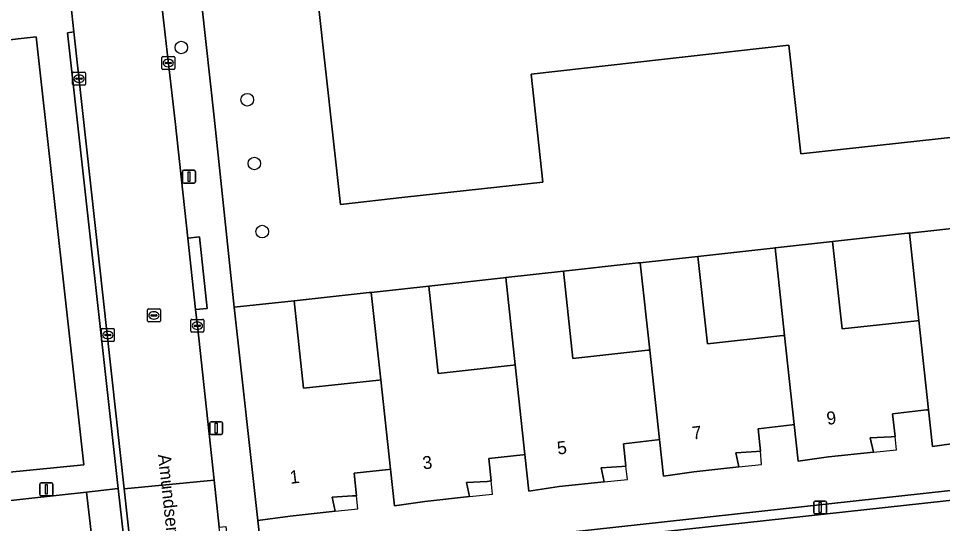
# Model space of a CAD drawing. Extents: x 161248 to 161848, y 384871 to 385383.
# Drawn here: x 161322.9 to 161394.3, y 385161 to 385200.1 of the extents above; entities that cross this region are included whole.
import ezdxf

# ---------------------------------------------------------------- set-up
doc = ezdxf.new("R2010")
doc.units = 0
for name, color, linetype in [('IMGEO_Boom', 7, 'Continuous'), ('IMGEO_Erf', 7, 'Continuous'), ('IMGEO_Kolk', 7, 'Continuous'), ('IMGEO_Lichtmast', 7, 'Continuous'), ('IMGEO_Openbare_ruimte_label', 7, 'Continuous'), ('IMGEO_Pand', 7, 'Continuous'), ('IMGEO_Pand_nummerreeks', 7, 'Continuous'), ('IMGEO_Pand_overbouw', 7, 'Continuous'), ('IMGEO_Rijbaan_lokaal_open', 7, 'Continuous'), ('IMGEO_Rioolput', 7, 'Continuous'), ('IMGEO_Voetpad_open', 7, 'Continuous')]:
    doc.layers.add(name, color=color, linetype=linetype)

msp = doc.modelspace()

# ---------------------------------------------------------------- linework, layer by layer
at = {"layer": 'IMGEO_Boom'}
for centre in [(161335.451, 385197.848), (161340.545, 385193.807), (161341.095, 385188.878), (161341.701, 385183.61)]:
    msp.add_circle(centre, 0.489, dxfattribs=at)
at = {"layer": 'IMGEO_Erf'}
for points in [[(161337.042, 385201.126), (161337.996, 385192.452), (161339.547, 385177.756), (161344.167, 385178.254), (161349.972, 385178.893), (161350.131, 385178.911), (161354.573, 385179.402), (161360.366, 385180.039), (161360.525, 385180.056), (161364.985, 385180.545), (161370.771, 385181.192), (161370.93, 385181.209), (161375.383, 385181.692), (161381.191, 385182.33), (161381.35, 385182.348), (161385.798, 385182.842), (161391.585, 385183.483), (161391.744, 385183.5), (161396.212, 385183.986)], [(161398.94, 385191.336), (161393.97, 385190.79), (161383.334, 385189.623), (161382.412, 385198.032), (161362.486, 385195.783), (161363.403, 385187.435), (161352.721, 385186.262), (161347.75, 385185.717), (161346.037, 385201.322)], [(161395.885, 385167.336), (161393.526, 385167.003), (161393.22, 385169.836), (161393.061, 385169.818), (161390.435, 385169.518), (161390.627, 385167.777), (161390.314, 385167.741), (161388.71, 385167.652), (161388.965, 385166.554), (161385.488, 385166.19), (161383.139, 385165.855), (161382.832, 385168.686), (161382.673, 385168.668), (161380.045, 385168.365), (161380.213, 385166.637), (161379.921, 385166.605), (161378.33, 385166.504), (161378.557, 385165.42), (161375.077, 385165.037), (161372.725, 385164.709), (161372.418, 385167.527), (161372.259, 385167.509), (161369.629, 385167.21), (161369.827, 385165.484), (161369.507, 385165.454), (161367.904, 385165.349), (161368.132, 385164.263), (161364.663, 385163.905), (161362.321, 385163.547), (161362.014, 385166.369), (161361.855, 385166.352), (161359.227, 385166.073), (161359.406, 385164.345), (161359.083, 385164.293), (161357.493, 385164.211), (161357.727, 385163.12), (161354.269, 385162.742), (161351.923, 385162.397), (161351.615, 385165.238), (161351.456, 385165.221), (161348.823, 385164.941), (161348.996, 385163.19), (161348.696, 385163.166), (161347.1, 385163.076), (161347.342, 385161.981), (161343.854, 385161.606), (161341.369, 385161.26), (161341.751, 385157.774), (161414.901, 385165.791)]]:
    msp.add_lwpolyline(points, dxfattribs=at)
for points in [[(161391.744, 385183.5), (161391.585, 385183.483), (161385.798, 385182.842), (161386.549, 385176.083), (161392.321, 385176.723), (161392.474, 385176.74)], [(161381.35, 385182.348), (161381.191, 385182.33), (161375.383, 385181.692), (161376.116, 385174.932), (161381.942, 385175.572), (161382.083, 385175.588)], [(161370.93, 385181.209), (161370.771, 385181.192), (161364.985, 385180.545), (161365.726, 385173.786), (161371.504, 385174.432), (161371.665, 385174.45)], [(161360.525, 385180.056), (161360.366, 385180.039), (161354.573, 385179.402), (161355.319, 385172.643), (161361.107, 385173.279), (161361.26, 385173.296)], [(161350.131, 385178.911), (161349.972, 385178.893), (161344.167, 385178.254), (161344.896, 385171.493), (161350.717, 385172.135), (161350.865, 385172.151)]]:
    msp.add_lwpolyline(points, close=True, dxfattribs=at)
at = {"layer": 'IMGEO_Kolk'}
for p, q in [((161333.937, 385196.219), (161333.937, 385197.071)), ((161334.012, 385197.145), (161334.864, 385197.145)), ((161334.196, 385196.639), (161334.196, 385196.651)), ((161334.634, 385196.602), (161334.236, 385196.602)), ((161334.239, 385196.688), (161334.637, 385196.688)), ((161334.425, 385196.925), (161334.45, 385196.925)), ((161334.68, 385196.651), (161334.68, 385196.639)), ((161334.938, 385197.071), (161334.938, 385196.219)), ((161327.046, 385195.008), (161327.046, 385195.86)), ((161327.121, 385195.934), (161327.973, 385195.934)), ((161328.047, 385195.86), (161328.047, 385195.008)), ((161334.864, 385196.145), (161334.012, 385196.145)), ((161334.448, 385196.365), (161334.423, 385196.365)), ((161327.305, 385195.428), (161327.305, 385195.44)), ((161327.743, 385195.391), (161327.345, 385195.391)), ((161327.348, 385195.477), (161327.746, 385195.477)), ((161327.557, 385195.154), (161327.532, 385195.154)), ((161327.534, 385195.714), (161327.559, 385195.714)), ((161327.789, 385195.44), (161327.789, 385195.428)), ((161327.973, 385194.934), (161327.121, 385194.934)), ((161336.192, 385175.901), (161336.192, 385176.753)), ((161336.267, 385176.827), (161337.119, 385176.827)), ((161336.68, 385176.607), (161336.705, 385176.607)), ((161337.193, 385176.753), (161337.193, 385175.901)), ((161329.269, 385175.193), (161329.269, 385176.045)), ((161329.344, 385176.119), (161330.196, 385176.119)), ((161329.757, 385175.899), (161329.782, 385175.899)), ((161330.27, 385176.045), (161330.27, 385175.193)), ((161337.119, 385175.827), (161336.267, 385175.827)), ((161336.451, 385176.321), (161336.451, 385176.333)), ((161336.889, 385176.284), (161336.491, 385176.284)), ((161336.494, 385176.37), (161336.892, 385176.37)), ((161336.703, 385176.047), (161336.678, 385176.047)), ((161336.935, 385176.333), (161336.935, 385176.321)), ((161330.196, 385175.119), (161329.344, 385175.119)), ((161329.528, 385175.613), (161329.528, 385175.625)), ((161329.966, 385175.576), (161329.568, 385175.576)), ((161329.571, 385175.662), (161329.969, 385175.662)), ((161329.78, 385175.339), (161329.755, 385175.339)), ((161330.012, 385175.625), (161330.012, 385175.613))]:
    msp.add_line(p, q, dxfattribs=at)
for points in [[(161333.937, 385196.219), (161333.937, 385197.071)], [(161334.012, 385197.145), (161334.864, 385197.145)], [(161334.938, 385197.071), (161334.938, 385196.219)], [(161327.046, 385195.008), (161327.046, 385195.86)], [(161327.121, 385195.934), (161327.973, 385195.934)], [(161328.047, 385195.86), (161328.047, 385195.008)], [(161334.864, 385196.145), (161334.012, 385196.145)], [(161327.973, 385194.934), (161327.121, 385194.934)], [(161336.192, 385175.901), (161336.192, 385176.753)], [(161336.267, 385176.827), (161337.119, 385176.827)], [(161337.193, 385176.753), (161337.193, 385175.901)], [(161329.269, 385175.193), (161329.269, 385176.045)], [(161329.344, 385176.119), (161330.196, 385176.119)], [(161330.27, 385176.045), (161330.27, 385175.193)], [(161337.119, 385175.827), (161336.267, 385175.827)], [(161330.196, 385175.119), (161329.344, 385175.119)]]:
    msp.add_lwpolyline(points, dxfattribs=at)
for centre, radius, start, end in [((161334.014, 385197.069), 0.0765, 91.55205, 178.44795), ((161334.014, 385197.069), 0.0765, 91.55205, 178.44795), ((161334.236, 385196.648), 0.0403, 85.87752, 175.75265), ((161334.233, 385196.638), 0.0366, 178.93798, 274.71019), ((161334.637, 385196.645), 0.043, 264.86636, 352.45326), ((161334.641, 385196.65), 0.0386, 1.73085, 96.63898), ((161334.862, 385197.069), 0.0765, 1.55205, 88.44795), ((161334.862, 385197.069), 0.0765, 1.55205, 88.44795), ((161327.123, 385195.858), 0.0765, 91.55205, 178.44795), ((161327.123, 385195.858), 0.0765, 91.55205, 178.44795), ((161327.971, 385195.858), 0.0765, 1.55205, 88.44795), ((161327.971, 385195.858), 0.0765, 1.55205, 88.44795), ((161334.014, 385196.221), 0.0765, 181.55205, 268.44795), ((161334.014, 385196.221), 0.0765, 181.55205, 268.44795), ((161334.862, 385196.221), 0.0765, 271.55205, 358.44795), ((161334.862, 385196.221), 0.0765, 271.55205, 358.44795), ((161327.345, 385195.437), 0.0403, 85.87752, 175.75265), ((161327.342, 385195.427), 0.0366, 178.93798, 274.71019), ((161327.746, 385195.434), 0.043, 264.86636, 352.45326), ((161327.75, 385195.439), 0.0386, 1.73085, 96.63898), ((161327.123, 385195.01), 0.0765, 181.55205, 268.44795), ((161327.123, 385195.01), 0.0765, 181.55205, 268.44795), ((161327.971, 385195.01), 0.0765, 271.55205, 358.44795), ((161327.971, 385195.01), 0.0765, 271.55205, 358.44795), ((161336.269, 385176.751), 0.0765, 91.55205, 178.44795), ((161336.269, 385176.751), 0.0765, 91.55205, 178.44795), ((161337.117, 385176.751), 0.0765, 1.55205, 88.44795), ((161337.117, 385176.751), 0.0765, 1.55205, 88.44795), ((161329.346, 385176.043), 0.0765, 91.55205, 178.44795), ((161329.346, 385176.043), 0.0765, 91.55205, 178.44795), ((161330.194, 385176.043), 0.0765, 1.55205, 88.44795), ((161330.194, 385176.043), 0.0765, 1.55205, 88.44795), ((161336.269, 385175.903), 0.0765, 181.55205, 268.44795), ((161336.269, 385175.903), 0.0765, 181.55205, 268.44795), ((161336.491, 385176.33), 0.0403, 85.87752, 175.75265), ((161336.488, 385176.32), 0.0366, 178.93798, 274.71019), ((161336.892, 385176.327), 0.043, 264.86636, 352.45326), ((161336.896, 385176.332), 0.0386, 1.73085, 96.63898), ((161337.117, 385175.903), 0.0765, 271.55205, 358.44795), ((161337.117, 385175.903), 0.0765, 271.55205, 358.44795), ((161329.346, 385175.195), 0.0765, 181.55205, 268.44795), ((161329.346, 385175.195), 0.0765, 181.55205, 268.44795), ((161329.568, 385175.622), 0.0403, 85.87752, 175.75265), ((161329.565, 385175.612), 0.0366, 178.93798, 274.71019), ((161329.969, 385175.619), 0.043, 264.86636, 352.45326), ((161329.973, 385175.624), 0.0386, 1.73085, 96.63898), ((161330.194, 385175.195), 0.0765, 271.55205, 358.44795), ((161330.194, 385175.195), 0.0765, 271.55205, 358.44795)]:
    msp.add_arc(centre, radius, start, end, dxfattribs=at)
for centre, major_axis, ratio, start_param, end_param in [((161334.424, 385196.645), (-0.387, 0.002), 0.722429, 4.712389, 7.853982), ((161334.449, 385196.645), (-0.39, 0.002), 0.717154, 1.570796, 4.712389), ((161327.533, 385195.434), (-0.387, 0.002), 0.722429, 4.712389, 7.853982), ((161327.558, 385195.434), (-0.39, 0.002), 0.717154, 1.570796, 4.712389), ((161336.679, 385176.327), (-0.387, 0.002), 0.722429, 4.712389, 7.853982), ((161336.704, 385176.327), (-0.39, 0.002), 0.717154, 1.570796, 4.712389), ((161329.756, 385175.619), (-0.387, 0.002), 0.722429, 4.712389, 7.853982), ((161329.781, 385175.619), (-0.39, 0.002), 0.717154, 1.570796, 4.712389)]:
    msp.add_ellipse(centre, major_axis=major_axis, ratio=ratio, start_param=start_param, end_param=end_param, dxfattribs=at)
at = {"layer": 'IMGEO_Lichtmast'}
for p, q in [((161335.547, 385187.463), (161335.547, 385188.263)), ((161335.547, 385188.263), (161335.547, 385187.463)), ((161335.647, 385188.363), (161336.437, 385188.363)), ((161336.437, 385188.363), (161335.647, 385188.363)), ((161336.537, 385188.263), (161336.537, 385187.463)), ((161336.537, 385187.463), (161336.537, 385188.263)), ((161336.437, 385187.363), (161335.647, 385187.363)), ((161335.647, 385187.363), (161336.437, 385187.363)), ((161337.649, 385168.012), (161337.649, 385168.812)), ((161337.649, 385168.812), (161337.649, 385168.012)), ((161337.749, 385168.912), (161338.539, 385168.912)), ((161338.539, 385168.912), (161337.749, 385168.912)), ((161338.639, 385168.812), (161338.639, 385168.012)), ((161338.639, 385168.012), (161338.639, 385168.812)), ((161338.539, 385167.912), (161337.749, 385167.912)), ((161337.749, 385167.912), (161338.539, 385167.912)), ((161324.52, 385163.278), (161324.52, 385164.078)), ((161324.52, 385164.078), (161324.52, 385163.278)), ((161324.62, 385164.178), (161325.41, 385164.178)), ((161325.41, 385164.178), (161324.62, 385164.178)), ((161325.51, 385164.078), (161325.51, 385163.278)), ((161325.51, 385163.278), (161325.51, 385164.078)), ((161325.41, 385163.178), (161324.62, 385163.178)), ((161324.62, 385163.178), (161325.41, 385163.178)), ((161384.342, 385161.877), (161384.342, 385162.677)), ((161384.342, 385162.677), (161384.342, 385161.877)), ((161384.442, 385162.777), (161385.232, 385162.777)), ((161385.232, 385162.777), (161384.442, 385162.777)), ((161385.332, 385162.677), (161385.332, 385161.877)), ((161385.332, 385161.877), (161385.332, 385162.677)), ((161385.232, 385161.777), (161384.442, 385161.777)), ((161384.442, 385161.777), (161385.232, 385161.777))]:
    msp.add_line(p, q, dxfattribs=at)
for points in [[(161335.967, 385188.238), (161336.117, 385188.238), (161336.117, 385187.488), (161335.967, 385187.488), (161335.967, 385188.238)], [(161338.069, 385168.787), (161338.219, 385168.787), (161338.219, 385168.037), (161338.069, 385168.037), (161338.069, 385168.787)], [(161324.94, 385164.053), (161325.09, 385164.053), (161325.09, 385163.303), (161324.94, 385163.303), (161324.94, 385164.053)], [(161384.762, 385162.652), (161384.912, 385162.652), (161384.912, 385161.902), (161384.762, 385161.902), (161384.762, 385162.652)]]:
    msp.add_lwpolyline(points, dxfattribs=at)
for centre, start, end in [((161335.647, 385188.263), 90, 180), ((161335.647, 385188.263), 90, 180), ((161336.437, 385188.263), 0, 90), ((161336.437, 385188.263), 360, 90), ((161335.647, 385187.463), 180, 270), ((161335.647, 385187.463), 180, 270), ((161336.437, 385187.463), 270, 0), ((161336.437, 385187.463), 270, 0), ((161337.749, 385168.812), 90, 180), ((161337.749, 385168.812), 90, 180), ((161338.539, 385168.812), 0, 90), ((161338.539, 385168.812), 360, 90), ((161337.749, 385168.012), 180, 270), ((161337.749, 385168.012), 180, 270), ((161338.539, 385168.012), 270, 0), ((161338.539, 385168.012), 270, 0), ((161324.62, 385164.078), 90, 180), ((161324.62, 385164.078), 90, 180), ((161325.41, 385164.078), 0, 90), ((161325.41, 385164.078), 360, 90), ((161324.62, 385163.278), 180, 270), ((161324.62, 385163.278), 180, 270), ((161325.41, 385163.278), 270, 0), ((161325.41, 385163.278), 270, 0), ((161384.442, 385162.677), 90, 180), ((161384.442, 385162.677), 90, 180), ((161385.232, 385162.677), 0, 90), ((161385.232, 385162.677), 360, 90), ((161384.442, 385161.877), 180, 270), ((161384.442, 385161.877), 180, 270), ((161385.232, 385161.877), 270, 0), ((161385.232, 385161.877), 270, 0)]:
    msp.add_arc(centre, 0.1, start, end, dxfattribs=at)
at = {"layer": 'IMGEO_Pand'}
msp.add_lwpolyline([(161346.037, 385201.322), (161347.75, 385185.717), (161352.721, 385186.262), (161363.403, 385187.435), (161362.486, 385195.783), (161382.412, 385198.032), (161383.334, 385189.623), (161393.97, 385190.79), (161398.94, 385191.336)], dxfattribs=at)
for points in [[(161402.139, 385184.643), (161401.98, 385184.625), (161402.725, 385177.866), (161396.948, 385177.226), (161396.212, 385183.986), (161391.744, 385183.5), (161392.474, 385176.74), (161393.22, 385169.836), (161393.526, 385167.003), (161395.885, 385167.336), (161399.358, 385167.712), (161399.123, 385168.803), (161400.714, 385168.901), (161401.024, 385168.918), (161400.824, 385170.684), (161403.479, 385170.951), (161403.638, 385170.967)], [(161392.474, 385176.74), (161392.321, 385176.723), (161386.549, 385176.083), (161385.798, 385182.842), (161381.35, 385182.348), (161382.083, 385175.588), (161382.832, 385168.686), (161383.139, 385165.855), (161385.488, 385166.19), (161388.965, 385166.554), (161388.71, 385167.652), (161390.314, 385167.741), (161390.627, 385167.777), (161390.435, 385169.518), (161393.061, 385169.818), (161393.22, 385169.836)], [(161382.083, 385175.588), (161381.942, 385175.572), (161376.116, 385174.932), (161375.383, 385181.692), (161370.93, 385181.209), (161371.665, 385174.45), (161372.418, 385167.527), (161372.725, 385164.709), (161375.077, 385165.037), (161378.557, 385165.42), (161378.33, 385166.504), (161379.921, 385166.605), (161380.213, 385166.637), (161380.045, 385168.365), (161382.673, 385168.668), (161382.832, 385168.686)], [(161371.665, 385174.45), (161371.504, 385174.432), (161365.726, 385173.786), (161364.985, 385180.545), (161360.525, 385180.056), (161361.26, 385173.296), (161362.014, 385166.369), (161362.321, 385163.547), (161364.663, 385163.905), (161368.132, 385164.263), (161367.904, 385165.349), (161369.507, 385165.454), (161369.827, 385165.484), (161369.629, 385167.21), (161372.259, 385167.509), (161372.418, 385167.527)], [(161361.26, 385173.296), (161361.107, 385173.279), (161355.319, 385172.643), (161354.573, 385179.402), (161350.131, 385178.911), (161350.865, 385172.151), (161351.615, 385165.238), (161351.923, 385162.397), (161354.269, 385162.742), (161357.727, 385163.12), (161357.493, 385164.211), (161359.083, 385164.293), (161359.406, 385164.345), (161359.227, 385166.073), (161361.855, 385166.352), (161362.014, 385166.369)], [(161350.865, 385172.151), (161350.717, 385172.135), (161344.896, 385171.493), (161344.167, 385178.254), (161339.547, 385177.756), (161341.369, 385161.26), (161343.854, 385161.606), (161347.342, 385161.981), (161347.1, 385163.076), (161348.696, 385163.166), (161348.996, 385163.19), (161348.823, 385164.941), (161351.456, 385165.221), (161351.615, 385165.238)]]:
    msp.add_lwpolyline(points, close=True, dxfattribs=at)
at = {"layer": 'IMGEO_Pand_overbouw'}
for points in [[(161390.627, 385167.777), (161390.314, 385167.741), (161388.71, 385167.652), (161388.965, 385166.554), (161390.741, 385166.74)], [(161380.213, 385166.637), (161379.921, 385166.605), (161378.33, 385166.504), (161378.557, 385165.42), (161380.313, 385165.613)], [(161369.827, 385165.484), (161369.507, 385165.454), (161367.904, 385165.349), (161368.132, 385164.263), (161369.946, 385164.45)], [(161359.406, 385164.345), (161359.083, 385164.293), (161357.493, 385164.211), (161357.727, 385163.12), (161359.513, 385163.315)], [(161348.996, 385163.19), (161348.696, 385163.166), (161347.1, 385163.076), (161347.342, 385161.981), (161349.097, 385162.17)]]:
    msp.add_lwpolyline(points, close=True, dxfattribs=at)
at = {"layer": 'IMGEO_Rijbaan_lokaal_open'}
for points in [[(161326.822, 385201.971), (161327.141, 385199.049), (161331.038, 385163.711), (161337.994, 385164.378), (161336.692, 385176.326), (161336.557, 385177.575), (161335.96, 385183.113), (161334.986, 385192.138), (161334.197, 385198.828), (161333.767, 385202.749)], [(161345.081, 385099.589), (161343.794, 385111.449), (161342.886, 385119.72), (161340.632, 385140.435), (161339.619, 385149.644), (161338.388, 385160.759), (161337.994, 385164.378), (161331.038, 385163.711), (161331.58, 385158.8), (161331.619, 385158.449), (161332.208, 385158.002), (161332.485, 385157.764)], [(161325.63, 385158.041), (161328.7, 385158.391), (161328.129, 385163.466), (161312.135, 385161.71)], [(161395.989, 385162.959), (161342.455, 385157.097), (161342.934, 385152.944), (161343.487, 385152.997), (161349.169, 385153.631), (161353.072, 385154.067), (161358.759, 385154.69), (161362.66, 385155.108), (161368.344, 385155.738), (161372.231, 385156.162), (161377.912, 385156.775), (161381.825, 385157.219), (161387.494, 385157.833), (161392.01, 385158.338), (161396.837, 385114.227)]]:
    msp.add_lwpolyline(points, dxfattribs=at)
at = {"layer": 'IMGEO_Rioolput'}
for p, q in [((161332.831, 385176.701), (161332.831, 385177.553)), ((161332.906, 385177.627), (161333.758, 385177.627)), ((161333.133, 385177.17), (161333.531, 385177.17)), ((161333.319, 385177.407), (161333.344, 385177.407)), ((161333.832, 385177.553), (161333.832, 385176.701)), ((161333.758, 385176.627), (161332.906, 385176.627)), ((161333.09, 385177.121), (161333.09, 385177.133)), ((161333.528, 385177.084), (161333.13, 385177.084)), ((161333.342, 385176.847), (161333.317, 385176.847)), ((161333.574, 385177.133), (161333.574, 385177.121))]:
    msp.add_line(p, q, dxfattribs=at)
for points in [[(161332.831, 385176.701), (161332.831, 385177.553)], [(161332.906, 385177.627), (161333.758, 385177.627)], [(161333.832, 385177.553), (161333.832, 385176.701)], [(161333.758, 385176.627), (161332.906, 385176.627)]]:
    msp.add_lwpolyline(points, dxfattribs=at)
for centre, radius, start, end in [((161332.908, 385177.551), 0.0765, 91.55205, 178.44795), ((161332.908, 385177.551), 0.0765, 91.55205, 178.44795), ((161333.13, 385177.13), 0.0403, 85.87752, 175.75265), ((161333.535, 385177.132), 0.0386, 1.73085, 96.63898), ((161333.756, 385177.551), 0.0765, 1.55205, 88.44795), ((161333.756, 385177.551), 0.0765, 1.55205, 88.44795), ((161332.908, 385176.703), 0.0765, 181.55205, 268.44795), ((161332.908, 385176.703), 0.0765, 181.55205, 268.44795), ((161333.127, 385177.12), 0.0366, 178.93798, 274.71019), ((161333.531, 385177.127), 0.043, 264.86636, 352.45326), ((161333.756, 385176.703), 0.0765, 271.55205, 358.44795), ((161333.756, 385176.703), 0.0765, 271.55205, 358.44795)]:
    msp.add_arc(centre, radius, start, end, dxfattribs=at)
for centre, major_axis, ratio, start_param, end_param in [((161333.318, 385177.127), (-0.387, 0.002), 0.722429, 4.712389, 7.853982), ((161333.343, 385177.127), (-0.39, 0.002), 0.717154, 1.570796, 4.712389)]:
    msp.add_ellipse(centre, major_axis=major_axis, ratio=ratio, start_param=start_param, end_param=end_param, dxfattribs=at)
at = {"layer": 'IMGEO_Voetpad_open'}
for points in [[(161312.135, 385161.71), (161328.129, 385163.466), (161330.574, 385163.733), (161326.646, 385198.993), (161327.141, 385199.049), (161326.822, 385201.971), (161321.575, 385250), (161319.33, 385271.321), (161319.259, 385272.292), (161319.265, 385273.638), (161319.391, 385274.978), (161319.678, 385276.452), (161318.759, 385276.732), (161319.247, 385278.182), (161319.902, 385279.684), (161320.689, 385281.122), (161321.6, 385282.484), (161322.63, 385283.759), (161323.77, 385284.937), (161324.411, 385284.249)], [(161333.767, 385202.749), (161334.197, 385198.828), (161334.986, 385192.138), (161335.96, 385183.113), (161336.864, 385183.211), (161337.461, 385177.673), (161336.557, 385177.575), (161336.692, 385176.326), (161337.994, 385164.378), (161338.388, 385160.759), (161338.884, 385160.814), (161339.251, 385157.497), (161341.751, 385157.774), (161341.369, 385161.26), (161339.547, 385177.756), (161337.996, 385192.452), (161337.042, 385201.126)], [(161319.925, 385201.199), (161311.354, 385200.24), (161310.083, 385200.098), (161284.477, 385197.232), (161284.861, 385194.419), (161292.512, 385195.314), (161298.583, 385195.971), (161298.591, 385195.9), (161306.323, 385196.762), (161306.263, 385197.297), (161312.214, 385197.961), (161318.164, 385198.625), (161318.232, 385198.013), (161324.218, 385198.681), (161327.91, 385165.578), (161321.918, 385164.982), (161315.846, 385164.304), (161315.641, 385166.137), (161311.253, 385165.674)], [(161414.901, 385165.791), (161341.751, 385157.774), (161341.838, 385157.038), (161342.455, 385157.097), (161395.989, 385162.959)], [(161343.678, 385049.095), (161341.217, 385071.409), (161341.195, 385071.608), (161340.694, 385071.554), (161340.168, 385076.316), (161340.67, 385076.371), (161340.643, 385076.62), (161331.619, 385158.449), (161331.58, 385158.8), (161331.129, 385158.749), (161330.574, 385163.733), (161328.129, 385163.466), (161328.7, 385158.391), (161337.698, 385076.275), (161338.273, 385071.053), (161327.126, 385070.008), (161326.877, 385072.057)]]:
    msp.add_lwpolyline(points, dxfattribs=at)
for points in [[(161324.218, 385198.681), (161318.232, 385198.013), (161318.505, 385195.567), (161318.847, 385192.508), (161319.188, 385189.45), (161319.529, 385186.391), (161319.87, 385183.333), (161320.212, 385180.274), (161320.553, 385177.216), (161320.894, 385174.157), (161321.235, 385171.099), (161321.577, 385168.04), (161321.918, 385164.982), (161327.91, 385165.578)], [(161327.141, 385199.049), (161326.646, 385198.993), (161330.574, 385163.733), (161331.129, 385158.749), (161331.58, 385158.8), (161331.038, 385163.711)], [(161336.557, 385177.575), (161337.461, 385177.673), (161336.864, 385183.211), (161335.96, 385183.113)]]:
    msp.add_lwpolyline(points, close=True, dxfattribs=at)

# ---------------------------------------------------------------- texts
at = {"layer": 'IMGEO_Openbare_ruimte_label'}
msp.add_text('Amundsenlaan', height=1, rotation=276.25793, dxfattribs=at).set_placement((161333.64, 385166.357))
at = {"layer": 'IMGEO_Pand_nummerreeks'}
for s, rotation, p in [('9', 6.8182, (161385.39, 385168.664)), ('7', 6.93852, (161374.992, 385167.525)), ('5', 7.00727, (161364.561, 385166.363)), ('3', 7.08749, (161354.16, 385165.216)), ('1', 6.88122, (161343.894, 385164.103))]:
    msp.add_text(s, height=1, rotation=rotation, dxfattribs=at).set_placement(p)

doc.saveas('drawing.dxf')
